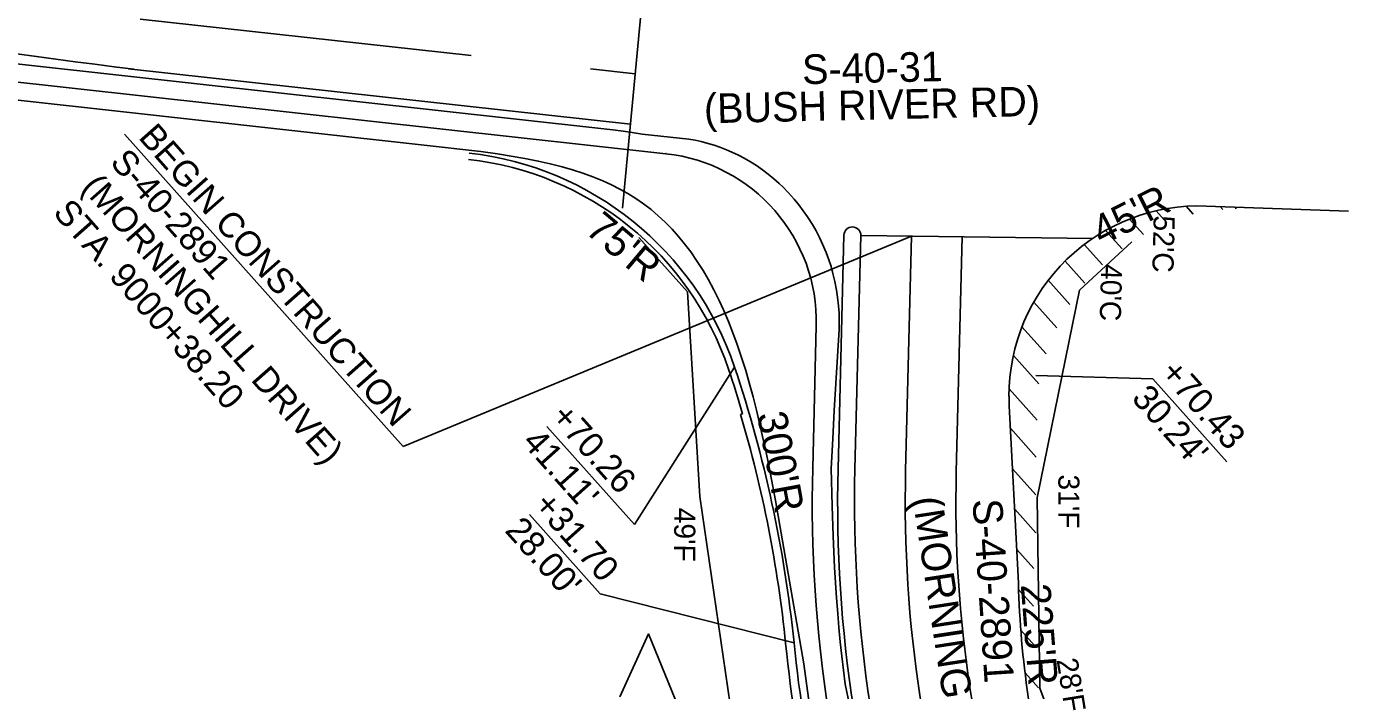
# Model space of a CAD drawing. Extents: x 1966090 to 1975830, y 788086 to 801233.
# Drawn here: x 1969155.5 to 1969468.5, y 799154.4 to 799311.6 of the extents above; entities that cross this region are included whole.
import ezdxf

# ---------------------------------------------------------------- set-up
doc = ezdxf.new("R2010")
doc.units = 0
for name, color, linetype in [('BR_PROPOSED_DRAINAGE', 7, 'Continuous'), ('RD_EX_Driveway_txCode', 7, 'Continuous'), ('RD_EX_GuardRail', 7, 'Continuous'), ('RD_EX_RW_TX', 7, 'Continuous'), ('RD_EX_SU_Gas', 7, 'Continuous'), ('RD_EX_SU_H2O', 7, 'Continuous'), ('RD_EX_Survey_Limits', 7, 'Continuous'), ('RD_PD_PaveShd', 7, 'Continuous'), ('RD_PD_RW_TX', 7, 'Continuous'), ('RD_Sketch10', 7, 'Continuous'), ('RD_Sketch6', 7, 'Continuous'), ('RD_Sketch8', 7, 'Continuous')]:
    doc.layers.add(name, color=color, linetype=linetype)

msp = doc.modelspace()

# ---------------------------------------------------------------- linework, layer by layer
at = {"layer": 'BR_PROPOSED_DRAINAGE'}
for p, q in [((1969300.49, 799261.65), (1969312.05, 799248.77)), ((1969417.24, 799260.63), (1969404.79, 799249.14)), ((1969312.05, 799248.77), (1969314.96, 799200.36)), ((1969404.79, 799249.14), (1969394.8, 799200.03)), ((1969314.96, 799200.36), (1969323.3, 799143.16)), ((1969394.8, 799200.03), (1969395.41, 799154.92)), ((1969395.41, 799154.92), (1969411.41, 799112.72))]:
    msp.add_line(p, q, dxfattribs=at)
at = {"layer": 'RD_EX_GuardRail'}
for p, q in [((1969306.93, 799281.48), (1969143.82, 799299.52)), ((1969341.68, 799207.06), (1969342.52, 799240.72))]:
    msp.add_line(p, q, dxfattribs=at)
for points in [[(1969081.06, 799310.74), (1969291.52, 799287.46), (1969294.34, 799287.13), (1969296.8, 799286.82), (1969298.9, 799286.51), (1969301.34, 799286.12), (1969312.38, 799284.89), (1969313.83, 799284.65), (1969315.25, 799284.35), (1969316.64, 799284.01), (1969318.34, 799283.51), (1969319.67, 799283.05), (1969321.29, 799282.43), (1969322.55, 799281.88), (1969324.1, 799281.14), (1969325.45, 799280.42), (1969326.92, 799279.56), (1969328.36, 799278.65), (1969329.76, 799277.67), (1969331.13, 799276.64), (1969332.45, 799275.55), (1969333.74, 799274.41), (1969334.67, 799273.52), (1969335.88, 799272.29), (1969337.31, 799270.68), (1969338.41, 799269.34), (1969339.45, 799267.96), (1969340.44, 799266.53), (1969341.6, 799264.7), (1969342.46, 799263.19), (1969343.27, 799261.65), (1969344.01, 799260.08), (1969344.85, 799258.08), (1969345.49, 799256.33), (1969346.01, 799254.75), (1969346.46, 799253.14), (1969346.93, 799251.19), (1969347.32, 799249.2), (1969347.57, 799247.52), (1969347.79, 799245.48), (1969347.91, 799243.75), (1969347.96, 799241.65), (1969347.92, 799239.88), (1969346.76, 799220.65), (1969346.4, 799213.97), (1969346.08, 799206.96), (1969346.29, 799198.1), (1969346.53, 799190.95), (1969346.87, 799183.48), (1969347.32, 799176.37), (1969347.6, 799172.65), (1969347.89, 799169.28), (1969348.21, 799165.91), (1969348.56, 799162.55), (1969348.95, 799159.2), (1969349.37, 799155.86), (1969350.37, 799150.98)], [(1969340.72, 799152.06), (1969340.18, 799156.05), (1969339.61, 799160.71), (1969334.54, 799189.82), (1969332.83, 799199.4), (1969331.25, 799207.64), (1969330.54, 799211.11), (1969329.8, 799214.56), (1969329.09, 799217.69), (1969328.34, 799220.8), (1969327.55, 799223.92), (1969326.79, 799226.71), (1969325.81, 799230.12), (1969324.84, 799233.21), (1969323.8, 799236.29), (1969322.79, 799239.05), (1969321.71, 799241.79), (1969320.55, 799244.51), (1969319.53, 799246.72), (1969318.28, 799249.25), (1969316.93, 799251.74), (1969315.73, 799253.79), (1969314.18, 799256.22), (1969312.79, 799258.23), (1969311.28, 799260.21), (1969309.9, 799261.89), (1969308.37, 799263.6), (1969306.78, 799265.23), (1969305.12, 799266.78), (1969303.41, 799268.23), (1969301.64, 799269.59), (1969299.82, 799270.86), (1969297.94, 799272.04), (1969296.01, 799273.12), (1969294.03, 799274.12), (1969292.01, 799275.04), (1969289.66, 799276), (1969287.26, 799276.87), (1969284.83, 799277.66), (1969282.36, 799278.37), (1969279.54, 799279.09), (1969276.69, 799279.73), (1969273.49, 799280.36), (1969270.27, 799280.92), (1969267.02, 799281.42), (1969263.11, 799281.96), (1969258.85, 799282.49), (1969253.26, 799283.14), (1969078.75, 799302.44)]]:
    msp.add_lwpolyline(points, dxfattribs=at)
for centre in [(1969306.93, 799281.48), (1969342.52, 799240.72), (1969341.68, 799207.06)]:
    msp.add_circle(centre, 0.0417, dxfattribs=at)
for centre, radius, start, end in [((1969302.54, 799241.72), 40, 358.558, 83.6883), ((1969665.13, 799198.91), 323.56, 178.558, 199.0518)]:
    msp.add_arc(centre, radius, start, end, dxfattribs=at)
at = {"layer": 'RD_EX_SU_Gas'}
for p, q in [((1969296.68, 799268.57), (1969301.71, 799322.3)), ((1969260.82, 799304.69), (1969182.48, 799313.35)), ((1969298.54, 799288.44), (1969179.69, 799301.59)), ((1969289.1, 799301.56), (1969299.66, 799300.39)), ((1969353.13, 799262.09), (1969407.96, 799261.42)), ((1969363.67, 799206.5), (1969365.07, 799261.94)), ((1969375.67, 799206.2), (1969377.07, 799261.8))]:
    msp.add_line(p, q, dxfattribs=at)
for centre, radius, start, end in [((1970191.83, 807096.05), 7859.87, 260.441445, 262.610548), ((1969665.13, 799198.91), 301.56, 178.558, 199.0518), ((1969665.13, 799198.91), 289.56, 178.558, 199.0518)]:
    msp.add_arc(centre, radius, start, end, dxfattribs=at)
at = {"layer": 'RD_EX_Survey_Limits'}
for p, q in [((1969347.67, 799206.91), (1969349.07, 799262.19)), ((1969351.67, 799206.81), (1969353.06, 799262.09))]:
    msp.add_line(p, q, dxfattribs=at)
for centre, radius, start, end in [((1969351.07, 799262.14), 2, 358.558, 178.558), ((1969665.13, 799198.91), 317.56, 178.558, 199.0518), ((1969665.13, 799198.91), 313.56, 178.558, 199.0518)]:
    msp.add_arc(centre, radius, start, end, dxfattribs=at)
at = {"layer": 'RD_PD_PaveShd'}
msp.add_line((1969325.08, 799219.91), (1969324.6, 799219.77), dxfattribs=at)
for centre, radius, start, end in [((1969038.78, 799135.45), 298, 5.7857, 16.4367), ((1969665.13, 799198.91), 331.56, 185.7857, 199.0518)]:
    msp.add_arc(centre, radius, start, end, dxfattribs=at)
at = {"layer": 'RD_PD_RW_TX'}
for centre, radius, start, end in [((1969252.08, 799207.06), 73.5, 18.5579, 83.6883), ((1969038.78, 799135.45), 298.5, 16.4367, 18.5579)]:
    msp.add_arc(centre, radius, start, end, dxfattribs=at)
at = {"layer": 'RD_Sketch10'}
msp.add_lwpolyline([(1969326.65, 799109.43), (1969302.8, 799167.77), (1969295.98, 799152.92)], dxfattribs=at)
at = {"layer": 'RD_Sketch6'}
for p, q in [((1969244.73, 799212.19), (1969178.73, 799286.11)), ((1969244.73, 799212.19), (1969365.07, 799261.94)), ((1969299.46, 799193.67), (1969323.18, 799230.93)), ((1969394.48, 799228.97), (1969422.22, 799228.15)), ((1969439.72, 799208.54), (1969422.22, 799228.15)), ((1969299.46, 799193.67), (1969278.72, 799216.9)), ((1969291.39, 799177.26), (1969274.63, 799196.03)), ((1969291.39, 799177.26), (1969337.25, 799165.69))]:
    msp.add_line(p, q, dxfattribs=at)
at = {"layer": 'RD_Sketch8'}
for p, q in [((1969422.95, 799267.96), (1969425.51, 799265.09)), ((1969430.05, 799269.02), (1969431.73, 799267.14)), ((1969434.8, 799269.09), (1969468.52, 799267.85)), ((1969438.14, 799268.97), (1969438.76, 799268.28)), ((1969441.86, 799268.4), (1969441.85, 799268.83)), ((1969416.66, 799266), (1969419.94, 799262.33)), ((1969411.02, 799263.31), (1969414.92, 799258.94)), ((1969405.95, 799259.98), (1969410.27, 799255.14)), ((1969401.42, 799256.04), (1969406.1, 799250.79)), ((1969397.43, 799251.51), (1969402.53, 799245.79)), ((1969394, 799246.33), (1969399.43, 799240.25)), ((1969391.2, 799240.46), (1969396.91, 799234.06)), ((1969389.17, 799233.72), (1969395.21, 799226.96)), ((1969388.2, 799221.75), (1969388.14, 799224)), ((1969388.17, 799225.84), (1969394.81, 799218.4)), ((1969390.33, 799181.41), (1969388.2, 799221.75)), ((1969388.48, 799216.48), (1969394.58, 799209.64)), ((1969388.98, 799206.91), (1969394.5, 799200.73)), ((1969389.49, 799197.33), (1969394.48, 799191.74)), ((1969389.99, 799187.76), (1969394.03, 799183.24)), ((1969390.41, 799178.28), (1969393.91, 799174.36)), ((1969390.93, 799168.69), (1969394.18, 799165.06)), ((1969391.93, 799158.56), (1969395.09, 799155.02))]:
    msp.add_line(p, q, dxfattribs=at)
for centre, radius, start, end in [((1969252.08, 799207.06), 75, 18.5579, 83.6883), ((1969433.13, 799224.12), 45, 87.8848, 180.1514), ((1969038.78, 799135.45), 300, 5.7857, 18.5579), ((1969615.29, 799185.73), 225, 181.1011, 194.816), ((1969665.13, 799198.91), 329.56, 185.7857, 199.0518)]:
    msp.add_arc(centre, radius, start, end, dxfattribs=at)

# ---------------------------------------------------------------- texts
at = {"layer": 'RD_EX_Driveway_txCode'}
for s, rotation, p in [("45'R", 26.9402, (1969410.07, 799259.59)), ("75'R", 319.8561, (1969287.52, 799262.94)), ("300'R", 280.5538, (1969328.46, 799219.81)), ('(MORNINGHILL DRIVE)', 278.6775, (1969365.29, 799199.87)), ('S-40-2891', 273.795, (1969379.49, 799199.58)), ("225'R", 274.4912, (1969390.91, 799179.45))]:
    msp.add_text(s, height=7, rotation=rotation, dxfattribs=at).set_placement(p)
at = {"layer": 'RD_EX_RW_TX'}
for s, rotation, p in [("52'C", 268.558, (1969422.4, 799266.91)), ("40'C", 268.558, (1969409.95, 799255.42)), ("31'F", 269.763, (1969399.82, 799205.56)), ("49'F", 269.763, (1969308.91, 799197.68)), ("28'F", 279.263, (1969399.37, 799161.68))]:
    msp.add_text(s, height=5, rotation=rotation, dxfattribs=at).set_placement(p)
at = {"layer": 'RD_EX_SU_H2O'}
for s, p in [('S-40-31', (1969339.24, 799297.93)), ('(BUSH RIVER RD)', (1969316, 799288.66))]:
    msp.add_text(s, height=7, rotation=1.2793, dxfattribs=at).set_placement(p)
at = {"layer": 'RD_Sketch6'}
for s, height, rotation, p in [('BEGIN CONSTRUCTION', 5.9996, 311.4287, (1969181.85, 799285.25)), ('S-40-2891', 6, 311.4287, (1969175.11, 799279.29)), ('(MORNINGHILL DRIVE)', 5.9996, 311.4287, (1969168.36, 799273.34)), ('STA. 9000+38.20', 5.9996, 311.4287, (1969161.61, 799267.38)), ('+70.43', 6, 311.7606, (1969423.63, 799229.41)), ("30.24'", 6, 311.7606, (1969416.92, 799223.41)), ('+70.26', 6, 311.7606, (1969279.38, 799219)), ("41.11'", 6, 311.7606, (1969272.67, 799213.01)), ('+31.70', 6, 311.7606, (1969275.3, 799198.12)), ("28.00'", 6, 311.7606, (1969268.58, 799192.13))]:
    msp.add_text(s, height=height, rotation=rotation, dxfattribs=at).set_placement(p)

doc.saveas('drawing.dxf')
